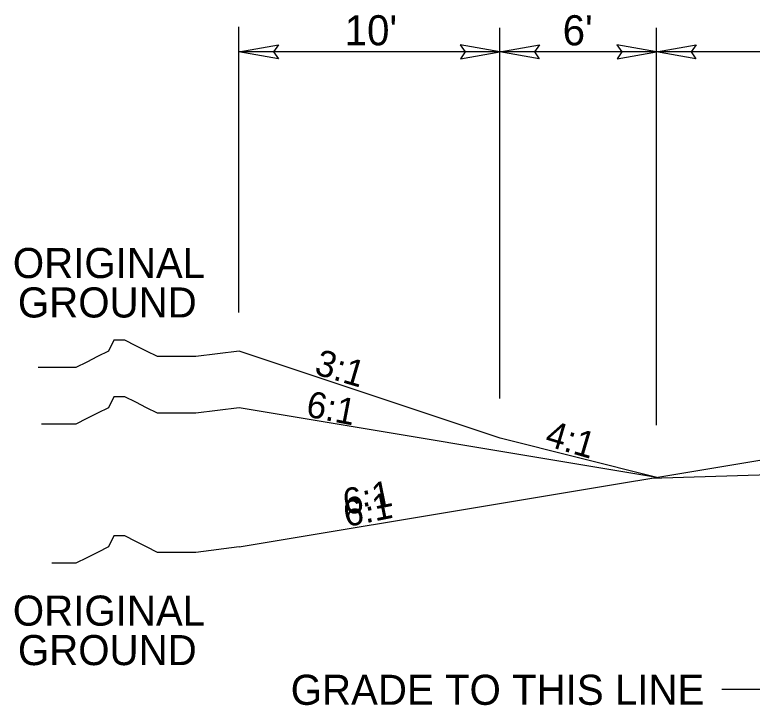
# Model space of a CAD drawing. Extents: x 2176156 to 2177167, y 76401 to 76644.
# Drawn here: x 2176939.51 to 2176967.78, y 76463.32 to 76489.78 of the extents above; entities that cross this region are included whole.
import ezdxf

# ---------------------------------------------------------------- set-up
doc = ezdxf.new("R2010")
doc.units = 0
for name, color, linetype in [('Exist Building', 7, 'Continuous'), ('Exist Roads Curbs', 7, 'Continuous'), ('Exist Roads EOP Other', 7, 'Continuous'), ('Exist Roads Soil', 7, 'Continuous'), ('Exist Structure Minor Culvert Topo', 7, 'Continuous'), ('Old_Level_1', 7, 'Continuous'), ('Old_Level_3', 7, 'Continuous')]:
    doc.layers.add(name, color=color, linetype=linetype)

msp = doc.modelspace()

# ---------------------------------------------------------------- linework, layer by layer
at = {"layer": 'Exist Building'}
msp.add_line((2176963.901, 76472.018), (2176998.106, 76473.085), dxfattribs=at)
at = {"layer": 'Exist Roads Curbs'}
for points in [[(2176948.119, 76476.888), (2176946.448, 76476.68), (2176946.031, 76476.68), (2176945.403, 76476.68), (2176944.986, 76476.68), (2176944.568, 76476.888), (2176944.15, 76477.097), (2176943.733, 76477.307), (2176943.315, 76477.307), (2176943.105, 76476.888), (2176942.688, 76476.68), (2176942.27, 76476.47), (2176941.852, 76476.262), (2176941.435, 76476.262), (2176941.017, 76476.262), (2176940.599, 76476.262), (2176940.404, 76476.262)], [(2176948.119, 76474.721), (2176946.448, 76474.513), (2176946.03, 76474.513), (2176945.403, 76474.513), (2176944.985, 76474.513), (2176944.568, 76474.721), (2176944.15, 76474.931), (2176943.732, 76475.14), (2176943.315, 76475.14), (2176943.105, 76474.721), (2176942.687, 76474.513), (2176942.27, 76474.303), (2176941.852, 76474.095), (2176941.434, 76474.095), (2176941.017, 76474.095), (2176940.599, 76474.095), (2176940.537, 76474.095)], [(2176948.119, 76469.388), (2176946.448, 76469.18), (2176946.031, 76469.18), (2176945.403, 76469.18), (2176944.986, 76469.18), (2176944.568, 76469.388), (2176944.15, 76469.597), (2176943.733, 76469.807), (2176943.315, 76469.807), (2176943.105, 76469.388), (2176942.688, 76469.18), (2176942.27, 76468.97), (2176941.852, 76468.762), (2176941.435, 76468.762), (2176941.017, 76468.762), (2176940.935, 76468.762)]]:
    msp.add_lwpolyline(points, dxfattribs=at)
at = {"layer": 'Exist Roads EOP Other'}
for p, q in [((2176958.119, 76473.554), (2176948.119, 76476.888)), ((2176964.119, 76472.054), (2176958.119, 76473.554))]:
    msp.add_line(p, q, dxfattribs=at)
at = {"layer": 'Exist Roads Soil'}
for p, q in [((2176964.119, 76472.054), (2176948.119, 76474.721)), ((2176948.119, 76469.388), (2176976.071, 76474.046))]:
    msp.add_line(p, q, dxfattribs=at)
at = {"layer": 'Old_Level_1'}
for points in [[(2176949.616, 76488.094), (2176948.106, 76488.354), (2176949.624, 76488.622), (2176949.431, 76488.354)], [(2176956.596, 76488.094), (2176958.106, 76488.354), (2176956.588, 76488.622), (2176956.781, 76488.354)], [(2176959.616, 76488.094), (2176958.106, 76488.354), (2176959.624, 76488.622), (2176959.431, 76488.354)], [(2176962.596, 76488.094), (2176964.106, 76488.354), (2176962.588, 76488.622), (2176962.781, 76488.354)], [(2176965.616, 76488.094), (2176964.106, 76488.354), (2176965.624, 76488.622), (2176965.431, 76488.354)]]:
    msp.add_lwpolyline(points, close=True, dxfattribs=at)
at = {"layer": 'Old_Level_3'}
for p, q in [((2176948.106, 76478.375), (2176948.106, 76489.308)), ((2176958.106, 76475.074), (2176958.106, 76489.282)), ((2176964.106, 76474.056), (2176964.106, 76489.282)), ((2176958.106, 76488.354), (2176948.106, 76488.354)), ((2176964.106, 76488.354), (2176958.106, 76488.354)), ((2176976.106, 76488.354), (2176964.106, 76488.354)), ((2176966.618, 76463.943), (2176976.186, 76463.943))]:
    msp.add_line(p, q, dxfattribs=at)

# ---------------------------------------------------------------- texts
at = {"layer": 'Exist Roads Curbs'}
for s, rotation, p in [('3:1', 343.5351, (2176950.954, 76476.02)), ('6:1', 349.1832, (2176950.635, 76474.392)), ('4:1', 343.5351, (2176959.786, 76473.288)), ('6:1', 11.4865, (2176952.208, 76470.6)), ('6:1', 11.4865, (2176952.221, 76470.143))]:
    msp.add_text(s, height=1.0064, rotation=rotation, dxfattribs=at).set_placement(p)
at = {"layer": 'Exist Structure Minor Culvert Topo'}
for s, height, p in [("10'", 1.1533, (2176952.158, 76488.606)), ("6'", 1.1533, (2176960.512, 76488.606)), ('ORIGINAL', 1.1533, (2176939.439, 76479.689)), ('GROUND', 1.1533, (2176939.633, 76478.178)), ('ORIGINAL', 1.1533, (2176939.439, 76466.371)), ('GROUND', 1.1533, (2176939.633, 76464.859)), ('GRADE TO THIS LINE', 1.15334, (2176950.088, 76463.338))]:
    msp.add_text(s, height=height, dxfattribs=at).set_placement(p)

doc.saveas('drawing.dxf')
